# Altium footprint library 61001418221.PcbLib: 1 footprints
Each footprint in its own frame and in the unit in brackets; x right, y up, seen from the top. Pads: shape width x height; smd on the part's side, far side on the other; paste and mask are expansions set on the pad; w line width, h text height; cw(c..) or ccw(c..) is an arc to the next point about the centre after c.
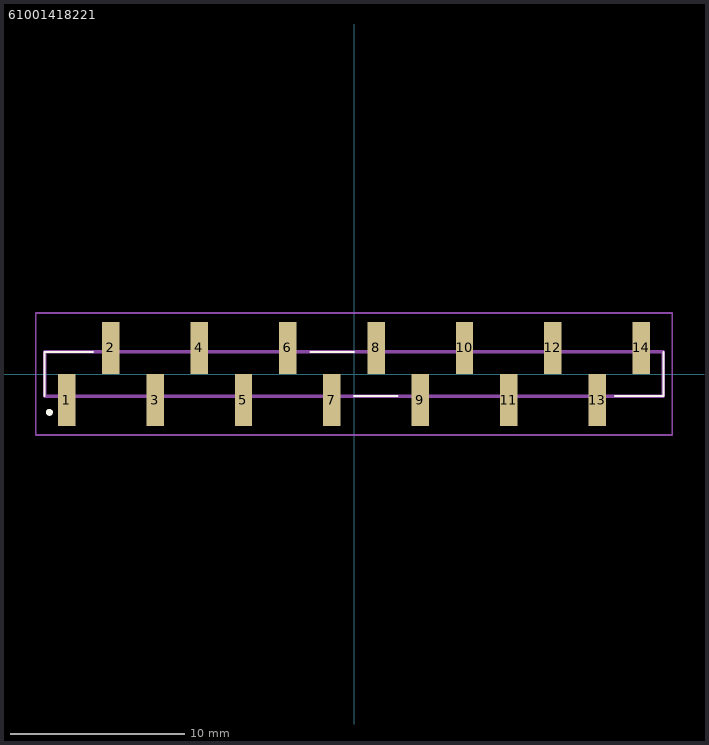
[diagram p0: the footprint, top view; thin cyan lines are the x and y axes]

## 61001418221 [mm]
pads (14):
  rect 1x3 smd: 1(-16.51,-1.5) 2(-13.97,1.5) 3(-11.43,-1.5) 4(-8.89,1.5) 5(-6.35,-1.5) 6(-3.81,1.5) 7(-1.27,-1.5) 8(1.27,1.5) 9(3.81,-1.5) 10(6.35,1.5) 11(8.89,-1.5) 12(11.43,1.5) 13(13.97,-1.5) 14(16.51,1.5)
Top Overlay:
  lines w0.1: -17.78,-1.27 -17.78,1.27 -15,1.27 ; -2.5,1.27 0,1.27 ; 0,-1.27 2.5,-1.27 ; 15,-1.27 17.78,-1.27 17.78,1.27
  lines w0.2: -17.5,-2.3 cw(c-17.5,-2.2) -17.5,-2.1 ; -17.5,-2.3 -17.5,-2.3 ; -17.5,-2.3 ccw(c-17.5,-2.2) -17.5,-2.1 ; -17.5,-2.1 -17.5,-2.1
Mechanical 15:
  lines w0.2: -17.78,-1.27 17.78,-1.27 17.78,1.27 -17.78,1.27 -17.78,-1.27
Mechanical 20:
  lines w0.1: -18.28,-3.5 18.28,-3.5 18.28,3.5 -18.28,3.5 -18.28,-3.5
